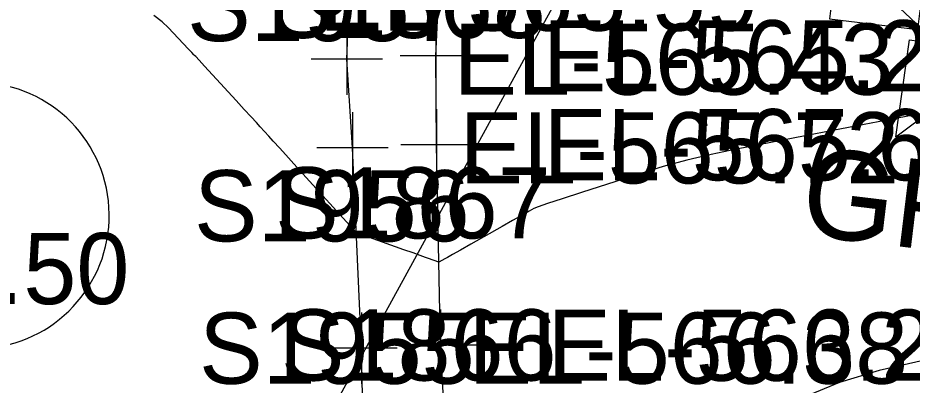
# Model space of a CAD drawing. Extents: x 1724534 to 1727318, y 657156 to 660047.
# Drawn here: x 1725381.4 to 1725431.6, y 658558.5 to 658579.2 of the extents above; entities that cross this region are included whole.
import ezdxf

# ---------------------------------------------------------------- set-up
doc = ezdxf.new("R2010")
doc.units = 0
for name, color, linetype in [('SURVEY - CENTERLINE - Preliminary Text', 7, 'Continuous'), ('SURVEY - CONTOURS - Intermediate with optional Text', 7, 'Continuous'), ('SURVEY - TRAFFIC CONTROL - Signs - Points - Elevations', 7, 'Continuous'), ('SURVEY - TRAFFIC CONTROL - Signs and Devices with Text', 7, 'Continuous'), ('SURVEY - TRANSPORTATION - Features', 7, 'Continuous'), ('SURVEY - TRANSPORTATION - Features - Points - Elevations', 7, 'Continuous'), ('SURVEY - TRANSPORTATION - Features - Points - Locators', 7, 'Continuous'), ('SURVEY - TRANSPORTATION - Features - Points - Numbers', 7, 'Continuous'), ('SURVEY - UTILITIES - Overhead Wire Crossings', 7, 'Continuous'), ('SURVEY - VEGETATION - Features - Points - Elevations', 7, 'Continuous'), ('SURVEY - VEGETATION - Features with Text', 7, 'Continuous')]:
    doc.layers.add(name, color=color, linetype=linetype)

msp = doc.modelspace()

# ---------------------------------------------------------------- linework, layer by layer
at = {"layer": 'SURVEY - CENTERLINE - Preliminary Text'}
msp.add_line((1725435.03, 658622.859), (1725332.926, 658436.26), dxfattribs=at)
at = {"layer": 'SURVEY - CONTOURS - Intermediate with optional Text'}
for points in [[(1725433.074, 658573.945), (1725430.901, 658573.533), (1725428.935, 658573.158), (1725427.178, 658572.821), (1725425.627, 658572.52), (1725421.771, 658571.768), (1725420.35, 658571.471), (1725418.979, 658571.145), (1725417.66, 658570.79), (1725416.391, 658570.406), (1725413.075, 658569.342), (1725411.975, 658568.986), (1725411.16, 658568.715), (1725410.632, 658568.531), (1725410.389, 658568.431), (1725410.123, 658568.28), (1725409.953, 658568.184), (1725409.644, 658568.009), (1725409.196, 658567.755), (1725408.608, 658567.422), (1725406.853, 658566.428), (1725406.269, 658566.096), (1725405.831, 658565.848), (1725405.54, 658565.684), (1725405.396, 658565.602), (1725405.066, 658565.415), (1725404.488, 658565.626), (1725404.308, 658565.691), (1725404.016, 658565.795), (1725403.613, 658565.939), (1725403.098, 658566.123), (1725400.434, 658567.072), (1725397.244, 658570.593), (1725396.623, 658571.278), (1725396.129, 658571.824), (1725395.761, 658572.23), (1725395.518, 658572.498), (1725395.041, 658573.024), (1725394.822, 658573.265), (1725394.523, 658573.592), (1725394.144, 658574.006), (1725393.685, 658574.505), (1725392.354, 658575.953), (1725391.918, 658576.428), (1725391.606, 658576.767), (1725391.418, 658576.971), (1725391.356, 658577.039), (1725391.355, 658577.04), (1725391.316, 658577.081), (1725391.198, 658577.206), (1725391.001, 658577.412), (1725389.89, 658578.584), (1725389.528, 658578.926), (1725389.072, 658579.291)], [(1725432.246, 658559.89), (1725429.772, 658559.338), (1725427.556, 658558.659), (1725425.597, 658557.852)]]:
    msp.add_lwpolyline(points, dxfattribs=at)
at = {"layer": 'SURVEY - TRAFFIC CONTROL - Signs and Devices with Text'}
msp.add_line((1725430.72, 658572.466), (1725436.934, 658577.146), dxfattribs=at)
msp.add_lwpolyline([(1725430.08, 658583.764), (1725427.598, 658584.067), (1725426.991, 658579.104), (1725431.954, 658578.497), (1725432.561, 658583.46), (1725430.08, 658583.764), (1725431.342, 658594.087), (1725429.407, 658594.323), (1725431.822, 658598.007), (1725433.278, 658593.85), (1725431.342, 658594.087)], dxfattribs=at)
msp.add_lwpolyline([(1725430.72, 658572.466), (1725431.487, 658577.913), (1725436.934, 658577.146), (1725436.167, 658571.699)], close=True, dxfattribs=at)
at = {"layer": 'SURVEY - TRANSPORTATION - Features'}
for points in [[(1725400.894, 658552.586), (1725400.722, 658560.59), (1725400.221, 658571.848), (1725399.893, 658576.832), (1725400.098, 658582.049), (1725399.251, 658589.894), (1725399.287, 658591.018), (1725392.146, 658591.982), (1725375.96, 658594.271), (1725361.07, 658596.084), (1725346.14, 658597.578), (1725331.263, 658599.505), (1725316.379, 658601.372), (1725301.242, 658603.491), (1725296.828, 658604.193), (1725291.122, 658605.02), (1725282.388, 658606.385), (1725277.767, 658607.035), (1725264.868, 658608.95), (1725250.092, 658611.569), (1725235.272, 658613.802), (1725224.442, 658615.275)], [(1725407.051, 658514.423), (1725406.111, 658532.587), (1725405.694, 658547.58), (1725405.6, 658552.767), (1725405.159, 658560.756), (1725404.935, 658572.024), (1725404.898, 658577.019), (1725405.123, 658581.786), (1725407.362, 658588.682), (1725407.715, 658589.907), (1725413.379, 658589.187), (1725422.977, 658587.952), (1725437.857, 658586.064), (1725459.261, 658583.438), (1725464.534, 658582.743), (1725469.842, 658582.102), (1725479.42, 658580.897), (1725489.321, 658579.676), (1725509.01, 658577.309), (1725525.471, 658575.592), (1725525.739, 658575.98), (1725538.364, 658574.489), (1725538.14, 658573.134)]]:
    msp.add_lwpolyline(points, dxfattribs=at)
at = {"layer": 'SURVEY - TRANSPORTATION - Features - Points - Locators'}
for p, q in [((1725404.898, 658579.019), (1725404.898, 658575.019)), ((1725399.893, 658578.832), (1725399.893, 658574.832)), ((1725406.898, 658577.019), (1725402.898, 658577.019)), ((1725401.893, 658576.832), (1725397.893, 658576.832)), ((1725404.935, 658574.024), (1725404.935, 658570.024)), ((1725400.221, 658573.848), (1725400.221, 658569.848)), ((1725406.935, 658572.024), (1725402.935, 658572.024)), ((1725402.221, 658571.848), (1725398.221, 658571.848)), ((1725400.722, 658562.59), (1725400.722, 658558.59)), ((1725405.159, 658562.756), (1725405.159, 658558.756)), ((1725402.722, 658560.59), (1725398.722, 658560.59)), ((1725407.159, 658560.756), (1725403.159, 658560.756))]:
    msp.add_line(p, q, dxfattribs=at)
at = {"layer": 'SURVEY - UTILITIES - Overhead Wire Crossings'}
msp.add_line((1725320.87, 658684.66), (1725490.651, 658522.766), dxfattribs=at)
at = {"layer": 'SURVEY - VEGETATION - Features with Text'}
msp.add_arc((1725379.072, 658568.043), 7.49, 273.117, 88.1173, dxfattribs=at)

# ---------------------------------------------------------------- texts
at = {"layer": 'SURVEY - TRAFFIC CONTROL - Signs - Points - Elevations'}
msp.add_text('EL-565.59', height=4, dxfattribs=at).set_placement((1725398.335, 658578.431))
at = {"layer": 'SURVEY - TRANSPORTATION - Features - Points - Elevations'}
for s, p in [('EL-565.28', (1725410.898, 658575.019)), ('EL-565.43', (1725405.893, 658574.832)), ('EL-565.62', (1725410.935, 658570.024)), ('EL-565.72', (1725406.221, 658569.848)), ('EL-566.38', (1725406.722, 658558.59)), ('EL-566.27', (1725411.159, 658558.756))]:
    msp.add_text(s, height=4, dxfattribs=at).set_placement(p)
at = {"layer": 'SURVEY - TRANSPORTATION - Features - Points - Numbers'}
for s, p in [('S1868', (1725395.6, 658578.024)), ('S1957', (1725390.933, 658577.848)), ('S1956', (1725391.324, 658566.59)), ('S1867', (1725395.871, 658566.756)), ('S1955', (1725391.606, 658558.586)), ('S1866', (1725396.202, 658558.767))]:
    msp.add_text(s, height=4, dxfattribs=at).set_placement(p)
at = {"layer": 'SURVEY - VEGETATION - Features - Points - Elevations'}
msp.add_text('EL-567.50', height=4, dxfattribs=at).set_placement((1725363.01, 658563.064))
at = {"layer": 'SURVEY - VEGETATION - Features with Text'}
msp.add_text('GRASS', height=5, rotation=353.1032, dxfattribs=at).set_placement((1725425.232, 658566.991))

doc.saveas('drawing.dxf')
